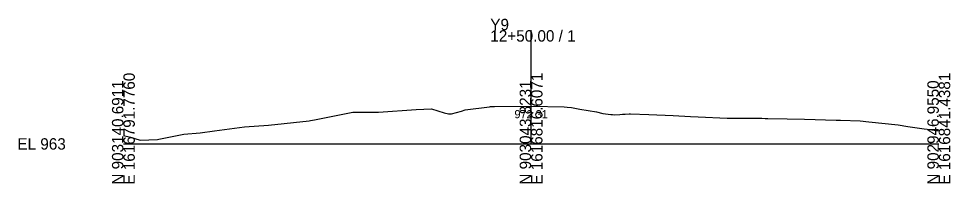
# Model space of a CAD drawing. Extents: x -26 to 1403, y -10 to 3021.
# Drawn here: x -25.7 to 202.8, y 2490.3 to 2530.8 of the extents above; entities that cross this region are included whole.
import ezdxf

# ---------------------------------------------------------------- set-up
doc = ezdxf.new("R2010")
doc.units = 0
for name, color, linetype in [('Exist Cross Section Cell', 7, 'Continuous'), ('Exist XS Center Line Elevation Label', 7, 'Continuous'), ('Exist XS Ground Line', 7, 'Continuous')]:
    doc.layers.add(name, color=color, linetype=linetype)

msp = doc.modelspace()

# ---------------------------------------------------------------- linework, layer by layer
at = {"layer": 'Exist Cross Section Cell'}
for p, q in [((100, 2500), (100, 2527.93)), ((0, 2500), (100, 2500)), ((100, 2500), (200, 2500))]:
    msp.add_line(p, q, dxfattribs=at)
at = {"layer": 'Exist XS Ground Line'}
for p, q in [((90.99, 2509.18), (100.02, 2509.31)), ((100.02, 2509.31), (108.14, 2509.08)), ((46.89, 2505.95), (56.24, 2507.77)), ((56.24, 2507.77), (62.55, 2507.82)), ((62.55, 2507.82), (71.79, 2508.45)), ((71.79, 2508.45), (75.59, 2508.6)), ((75.59, 2508.6), (78.72, 2507.66)), ((78.72, 2507.66), (79.77, 2507.37)), ((79.77, 2507.37), (80.52, 2507.37)), ((80.52, 2507.37), (82.93, 2508.08)), ((82.93, 2508.08), (83.84, 2508.34)), ((83.84, 2508.34), (89.76, 2509.13)), ((89.76, 2509.13), (90.07, 2509.17)), ((90.07, 2509.17), (90.99, 2509.18)), ((108.14, 2509.08), (108.87, 2509.06)), ((108.87, 2509.06), (109.9, 2508.91)), ((109.9, 2508.91), (111.99, 2508.56)), ((111.99, 2508.56), (116.03, 2507.91)), ((116.03, 2507.91), (117.61, 2507.5)), ((117.61, 2507.5), (119.56, 2507.23)), ((119.56, 2507.23), (119.99, 2507.22)), ((119.99, 2507.22), (120.52, 2507.14)), ((120.52, 2507.14), (121.73, 2507.25)), ((121.73, 2507.25), (122.43, 2507.29)), ((122.43, 2507.29), (123.06, 2507.33)), ((123.06, 2507.33), (124.08, 2507.42)), ((124.08, 2507.42), (124.39, 2507.41)), ((124.39, 2507.41), (128.88, 2507.23)), ((128.88, 2507.23), (134.85, 2507.01)), ((134.85, 2507.01), (139.06, 2506.75)), ((35.59, 2504.61), (45.58, 2505.7)), ((45.58, 2505.7), (45.92, 2505.73)), ((45.92, 2505.73), (46.89, 2505.95)), ((139.06, 2506.75), (141.01, 2506.63)), ((141.01, 2506.63), (148.13, 2506.34)), ((148.13, 2506.34), (149.69, 2506.3)), ((149.69, 2506.3), (156.59, 2506.29)), ((156.59, 2506.29), (157.44, 2506.27)), ((157.44, 2506.27), (158.04, 2506.26)), ((158.04, 2506.26), (162.81, 2506.15)), ((162.81, 2506.15), (167.09, 2506.08)), ((167.09, 2506.08), (174.84, 2505.84)), ((174.84, 2505.84), (175.93, 2505.81)), ((175.93, 2505.81), (180.72, 2505.67)), ((180.72, 2505.67), (182.88, 2505.44)), ((182.88, 2505.44), (190.04, 2504.67)), ((14.83, 2502.36), (18.82, 2502.76)), ((18.82, 2502.76), (22.31, 2503.25)), ((22.31, 2503.25), (29.68, 2504.21)), ((29.68, 2504.21), (35.59, 2504.61)), ((190.04, 2504.67), (192.37, 2504.31)), ((192.37, 2504.31), (196.45, 2503.72)), ((196.45, 2503.72), (197.15, 2503.63)), ((197.15, 2503.63), (200, 2503.25)), ((0, 2502.1), (1.72, 2501.62)), ((1.72, 2501.62), (4.13, 2500.91)), ((4.13, 2500.91), (8.34, 2501.12)), ((8.34, 2501.12), (8.7, 2501.14)), ((8.7, 2501.14), (9.13, 2501.23)), ((9.13, 2501.23), (14.83, 2502.36))]:
    msp.add_line(p, q, dxfattribs=at)

# ---------------------------------------------------------------- texts
at = {"layer": 'Exist Cross Section Cell'}
for s, p in [('Y9', (90, 2527.93)), ('12+50.00 / 1', (90, 2525.13)), ('EL 963', (-26, 2498.6))]:
    msp.add_text(s, height=2.8, dxfattribs=at).set_placement(p)
for s, p in [('E 1616791.7760', (2.8, 2490)), ('E 1616816.6071', (102.8, 2490)), ('E 1616841.4381', (202.8, 2490)), ('N 903140.6911', (0, 2490)), ('N 903043.8231', (100, 2490)), ('N 902946.9550', (200, 2490))]:
    msp.add_text(s, height=2.8, rotation=90, dxfattribs=at).set_placement(p)
at = {"layer": 'Exist XS Center Line Elevation Label'}
msp.add_text('972.31', height=2, dxfattribs=at).set_placement((95.92, 2506.31))

doc.saveas('drawing.dxf')
